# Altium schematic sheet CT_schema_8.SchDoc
size 274 x 160 mm
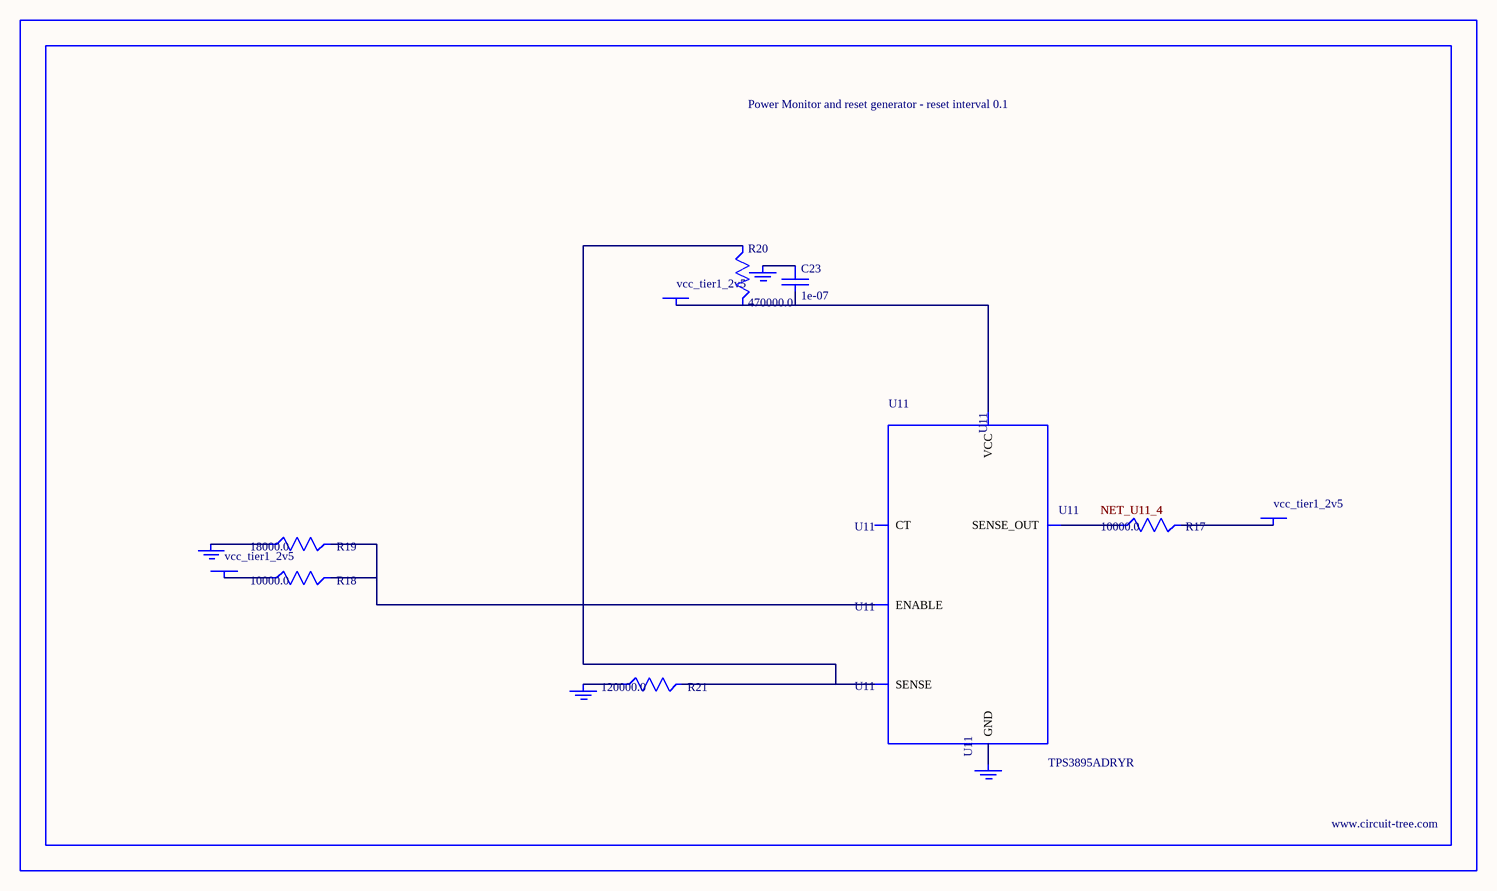
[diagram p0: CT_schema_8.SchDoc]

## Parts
BORDER7  (no value)
C23  1e-07  [C0402]
GND_INSTANCE_7_0  (no value)
GND_INSTANCE_7_1  (no value)
GND_INSTANCE_7_2  (no value)
GND_INSTANCE_7_3  (no value)
POWER_INSTANCE_7_0  vcc_tier1_2v5
POWER_INSTANCE_7_1  vcc_tier1_2v5
POWER_INSTANCE_7_2  vcc_tier1_2v5
R17  10000.0  [R0603]
R18  10000.0  [R0603]
R19  18000.0  [R0603]
R20  470000.0  [R0603]
R21  120000.0  [R0603]
U11  TPS3895ADRYR  [SON-6]

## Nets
NetC23_1: C23.1 GND_INSTANCE_7_2.0(GND)
NetC23_2: C23.2 POWER_INSTANCE_7_2.0(PWR) R20.2 U11.6(VCC)
NetGND_INSTANCE_7_0_0: GND_INSTANCE_7_0.0(GND) R19.1
NetGND_INSTANCE_7_1_0: GND_INSTANCE_7_1.0(GND) R21.1
NetGND_INSTANCE_7_3_0: GND_INSTANCE_7_3.0(GND) U11.2(GND)
NetPOWER_INSTANCE_7_0_0: POWER_INSTANCE_7_0.0(PWR) R18.1
NetPOWER_INSTANCE_7_1_0: POWER_INSTANCE_7_1.0(PWR) R17.2
NetR17_1: R17.1 U11.4(SENSE_OUT)
NetR18_2: R18.2 R19.2 U11.1(ENABLE)
NetR20_1: R20.1 R21.2 U11.3(SENSE)

Not connected (* = marked no-connect by the designer): U11 5(CT)

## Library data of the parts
BORDER7 = BORDER_PAGE7
C23 = C0402C104K3RACTU
GND_INSTANCE_7_0-GND_INSTANCE_7_3 = GND
POWER_INSTANCE_7_0-POWER_INSTANCE_7_2 = PWR
R17 R18 = RC0603JR-0710KL
R19 = RC0603JR-0718KL
R20 = RC0603JR-07470KL
R21 = RC0603JR-07120KL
